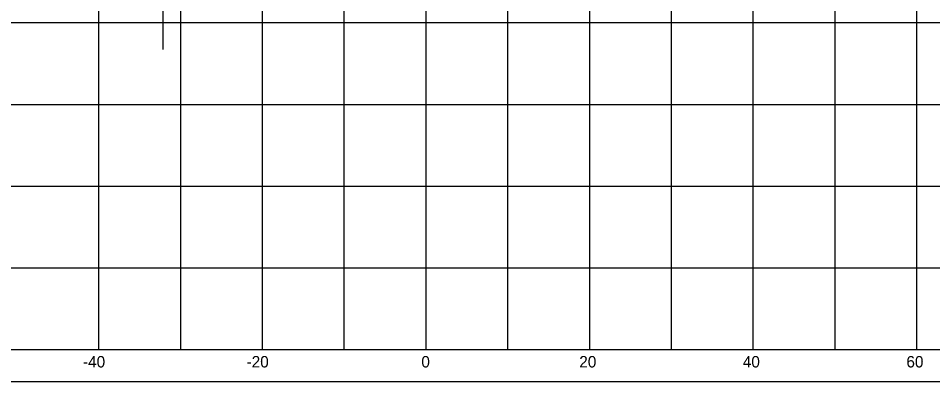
# Model space of a CAD drawing. Extents: x 1131015 to 1136271, y 133453 to 174329.
# Drawn here: x 1132290.6 to 1132402.4, y 157605.7 to 157650.2 of the extents above; entities that cross this region are included whole.
import ezdxf

# ---------------------------------------------------------------- set-up
doc = ezdxf.new("R2010")
doc.units = 0
for name, color, linetype in [('DESIGN - EARTHWORK - Excavation Limit Lines', 7, 'Continuous'), ('DESIGN - SHEET - Corner Text', 7, 'Continuous'), ('DESIGN - SHEET - Linework', 7, 'Continuous'), ('DESIGN - SHEET - Plot Shape', 7, 'Continuous')]:
    doc.layers.add(name, color=color, linetype=linetype)

msp = doc.modelspace()

# ---------------------------------------------------------------- linework, layer by layer
at = {"layer": 'DESIGN - EARTHWORK - Excavation Limit Lines'}
msp.add_line((1132308.26, 157698.88), (1132308.26, 157646.38), dxfattribs=at)
at = {"layer": 'DESIGN - SHEET - Linework'}
for p, q in [((1132300.46, 157609.66), (1132300.46, 157819.66)), ((1132310.46, 157609.66), (1132310.46, 157819.66)), ((1132320.46, 157609.66), (1132320.46, 157819.66)), ((1132330.46, 157609.66), (1132330.46, 157819.66)), ((1132340.46, 157609.66), (1132340.46, 157819.66)), ((1132350.46, 157609.66), (1132350.46, 157819.66)), ((1132360.46, 157609.66), (1132360.46, 157819.66)), ((1132370.46, 157609.66), (1132370.46, 157819.66)), ((1132380.46, 157609.66), (1132380.46, 157819.66)), ((1132390.46, 157609.66), (1132390.46, 157819.66)), ((1132400.46, 157609.66), (1132400.46, 157819.66)), ((1132190.46, 157649.66), (1132490.46, 157649.66)), ((1132190.46, 157639.66), (1132490.46, 157639.66)), ((1132190.46, 157629.66), (1132490.46, 157629.66)), ((1132190.46, 157619.66), (1132490.46, 157619.66))]:
    msp.add_line(p, q, dxfattribs=at)
msp.add_lwpolyline([(1132190.46, 157819.66), (1132190.46, 157609.66), (1132490.46, 157609.66), (1132490.46, 157819.66)], dxfattribs=at)
at = {"layer": 'DESIGN - SHEET - Plot Shape'}
msp.add_lwpolyline([(1132170.46, 157823.6), (1132510.46, 157823.6), (1132510.46, 157605.72), (1132170.46, 157605.72)], close=True, dxfattribs=at)

# ---------------------------------------------------------------- texts
at = {"layer": 'DESIGN - SHEET - Corner Text'}
for s, p in [('-40', (1132298.51, 157607.46)), ('-20', (1132318.51, 157607.46)), ('0', (1132339.88, 157607.46)), ('20', (1132359.19, 157607.46)), ('40', (1132379.19, 157607.46)), ('60', (1132399.19, 157607.46))]:
    msp.add_text(s, height=1.4, dxfattribs=at).set_placement(p)

doc.saveas('drawing.dxf')
